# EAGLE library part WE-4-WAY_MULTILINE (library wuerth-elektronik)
Multiline EMI Suppression Ferrite - Filter for common mode or differential mode - High rated current with typ. 4 A -- Perfect suitable for absorption of common or differential mode interferences in the field of EMC -- High current DC output filters of power supplies e.g. battery chargers, industrial power supplies
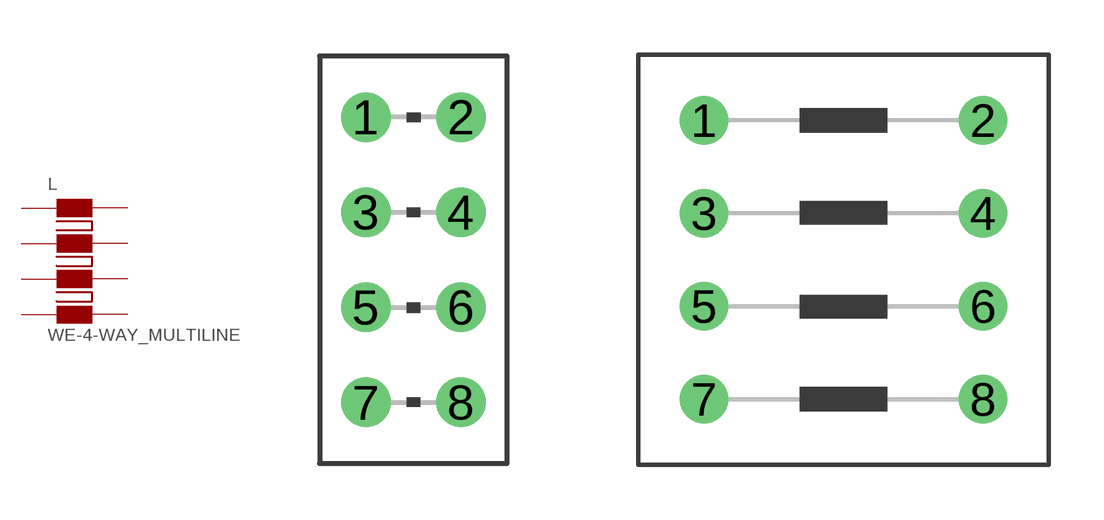
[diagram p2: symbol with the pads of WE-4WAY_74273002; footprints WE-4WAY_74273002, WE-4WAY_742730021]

Designator prefix L

## WE-4-WAY_MULTILINE_74273002  [WE-4WAY_74273002]
1  1  pas
2  2  pas
3  3  pas
4  4  pas
5  5  pas
6  6  pas
7  7  pas
8  8  pas

## WE-4-WAY_MULTILINE_742730021  [WE-4WAY_742730021]
Pads as for WE-4WAY_74273002

## WE-4-WAY_MULTILINE_742730022  [WE-4WAY_742730022]
Pads as for WE-4WAY_74273002

## WE-4-WAY_MULTILINE_742730023  [WE-4WAY_742730023]
Pads as for WE-4WAY_74273002

## Footprint WE-4WAY_74273002 (pad centres in mm)
Multiline Ferrite 4-way
drill 0.813 round: 1 -1.27,3.81; 2 1.27,3.81; 3 -1.27,1.27; 4 1.27,1.27; 5 -1.27,-1.27; 6 1.27,-1.27; 7 -1.27,-3.81; 8 1.27,-3.81

## Footprint WE-4WAY_742730021 (pad centres in mm)
Multiline Ferrite 4-way
drill 0.813 round: 1 -3.81,3.81; 2 3.81,3.81; 3 -3.81,1.27; 4 3.81,1.27; 5 -3.81,-1.27; 6 3.81,-1.27; 7 -3.81,-3.81; 8 3.81,-3.81

## Footprint WE-4WAY_742730022 (pad centres in mm)
Multiline Ferrite 4-way
drill 0.813 round: 1 -3.81,3.81; 2 3.81,3.81; 3 -3.81,1.27; 4 3.81,1.27; 5 -3.81,-1.27; 6 3.81,-1.27; 7 -3.81,-3.81; 8 3.81,-3.81

## Footprint WE-4WAY_742730023 (pad centres in mm)
Multiline Ferrite 4-way
drill 0.813 round: 1 -3.81,3.81; 2 3.81,3.81; 3 -3.81,1.27; 4 3.81,1.27; 5 -3.81,-1.27; 6 3.81,-1.27; 7 -3.81,-3.81; 8 3.81,-3.81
